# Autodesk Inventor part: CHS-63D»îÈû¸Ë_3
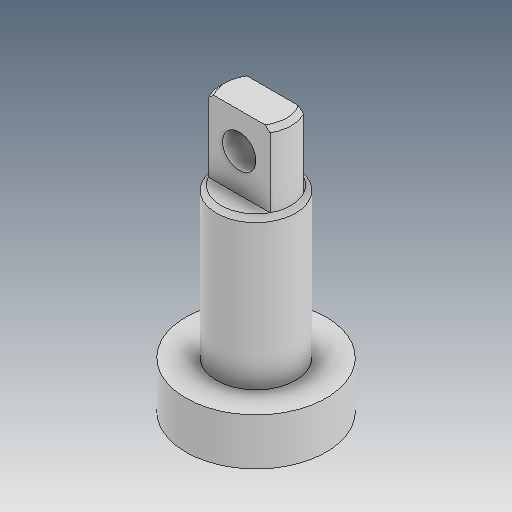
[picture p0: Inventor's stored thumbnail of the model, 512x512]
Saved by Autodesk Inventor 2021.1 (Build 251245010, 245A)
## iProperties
Created: 2019-05
Part Number: CHS-63D»îÈû¸Ë_3
Material: Ogólny
Document SubType Name: Modeling
Designer: user
Density: 1 g/cm^3
Appearance: Domyślna
Author: user
Revision Number: ÈÎºÎ
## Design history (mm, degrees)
feature "ÊäÈë1"
feature "ÊäÈë2"
node "Bryła1"
node "Bryła2"
